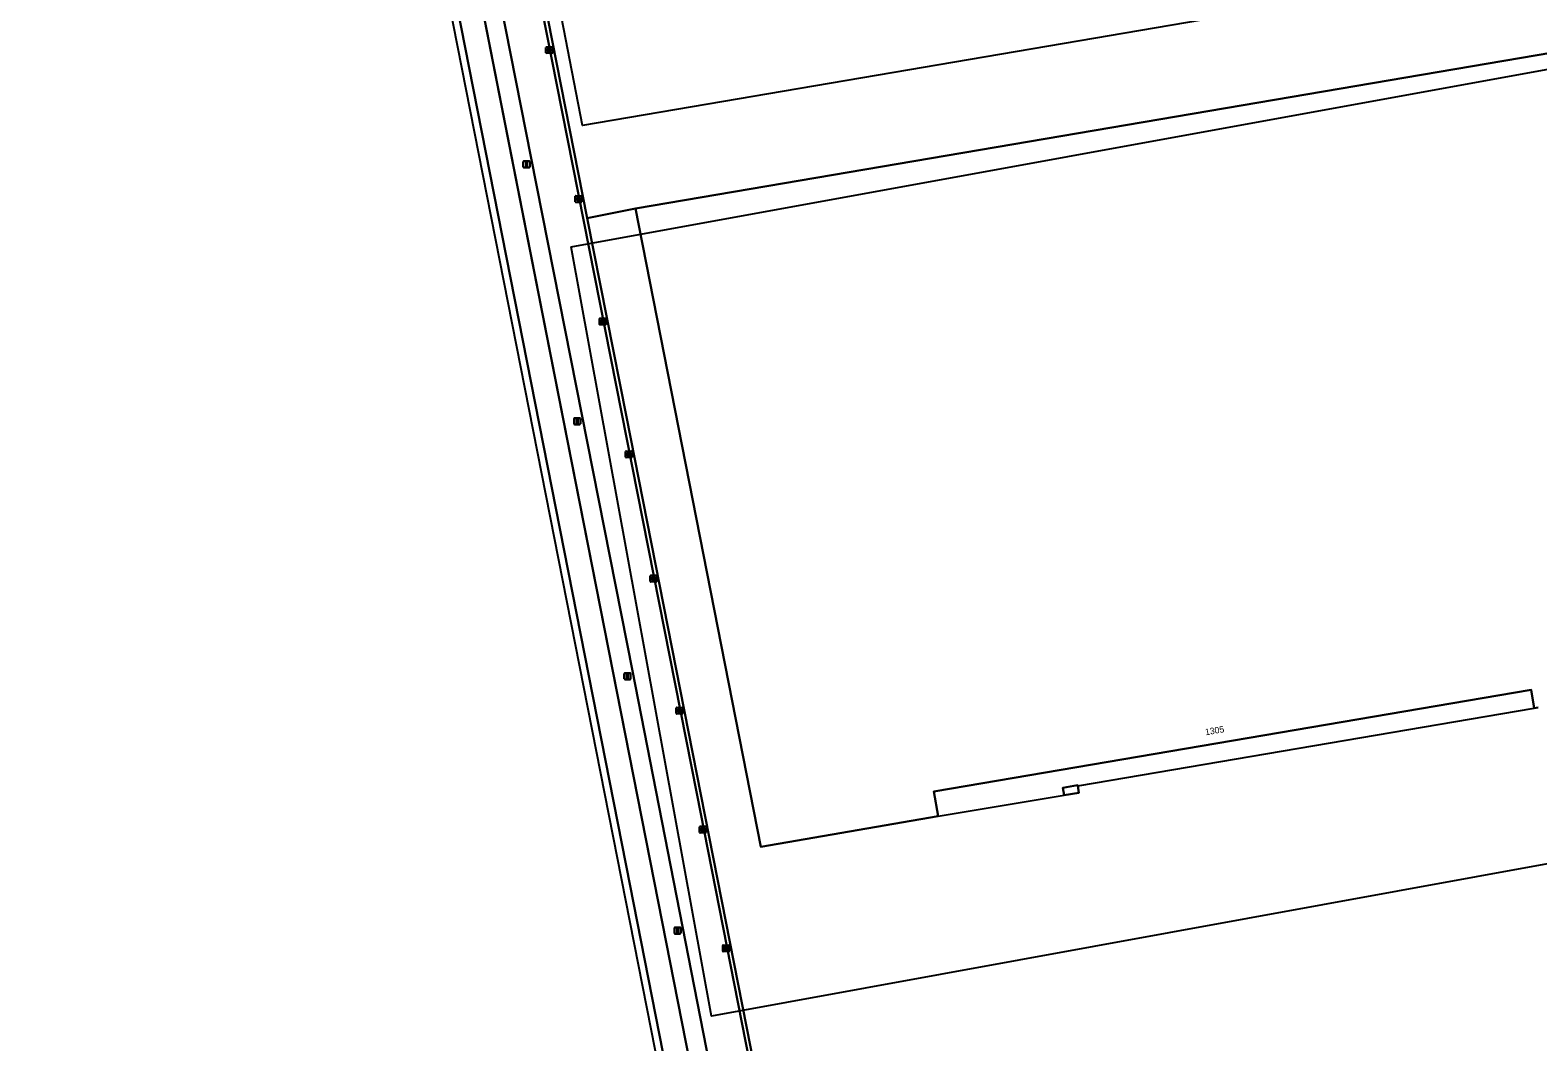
# Model space of a CAD drawing. Extents: x 154324 to 155744, y 382937 to 384188.
# Drawn here: x 154329.4 to 154562, y 383124 to 383280 of the extents above; entities that cross this region are included whole.
import ezdxf

# ---------------------------------------------------------------- set-up
doc = ezdxf.new("R2010")
doc.units = 0
for name, color, linetype in [('IMGEO_Bouwland', 7, 'Continuous'), ('IMGEO_Erf', 7, 'Continuous'), ('IMGEO_Groenvoorziening', 7, 'Continuous'), ('IMGEO_Hek', 7, 'Continuous'), ('IMGEO_Kolk', 7, 'Continuous'), ('IMGEO_Lichtmast', 7, 'Continuous'), ('IMGEO_Loofbos', 7, 'Continuous'), ('IMGEO_Pand', 7, 'Continuous'), ('IMGEO_Pand_nummerreeks', 7, 'Continuous'), ('IMGEO_Pand_overbouw', 7, 'Continuous'), ('IMGEO_Pand_vergunning_verleend', 7, 'Continuous'), ('IMGEO_Rijbaan_lokaal_gesloten', 7, 'Continuous')]:
    doc.layers.add(name, color=color, linetype=linetype)

msp = doc.modelspace()

# ---------------------------------------------------------------- linework, layer by layer
at = {"layer": 'IMGEO_Bouwland'}
for points in [[(154412.15, 383654.94), (154329.44, 383637.33), (154329.96, 383634.71), (154335.86, 383605.18), (154395.89, 383300.08), (154425.66, 383148.76), (154440.92, 383071.1), (154441.6, 383070.12), (154443.07, 383067.76), (154443.58, 383063.68), (154444.38, 383057.2), (154444.57, 383055.85), (154438.63, 383057.42), (154438.84, 383056.38)], [(154461.51, 382981.55), (154450.87, 383035.65), (154439.15, 383095.25), (154422.31, 383181.22), (154406.72, 383260.28), (154396.48, 383312.17), (154394.42, 383322.32), (154392.95, 383329.96)], [(154562.03, 383175.54), (154561.39, 383175.43), (154560.93, 383178.26), (154468.8, 383162.6), (154469.46, 383158.8), (154442.14, 383154.08), (154422.8, 383252.54), (154415.36, 383251.02), (154421.39, 383220.37), (154444.99, 383100.45), (154464.56, 383001.13), (154467.07, 382988.35)]]:
    msp.add_lwpolyline(points, dxfattribs=at)
msp.add_lwpolyline([(154491.18, 383162.38), (154488.9, 383162.01), (154488.72, 383163.17), (154490.98, 383163.56), (154490.99, 383163.49)], close=True, dxfattribs=at)
at = {"layer": 'IMGEO_Erf'}
msp.add_lwpolyline([(154401.25, 383322.6), (154415.36, 383251.02), (154422.8, 383252.54), (154564.29, 383276.58), (154564.29, 383276.6), (154571.56, 383277.87), (154570.67, 383283.11), (154571.25, 383283.17), (154566.84, 383309.22), (154557.23, 383365.65)], dxfattribs=at)
at = {"layer": 'IMGEO_Groenvoorziening'}
msp.add_lwpolyline([(154331.28, 383603.09), (154331.81, 383600.36), (154332.89, 383600.85), (154421.98, 383148.04), (154436.08, 383076.28), (154434.86, 383076.6), (154435.67, 383072.5), (154440.92, 383071.1), (154425.66, 383148.76), (154395.89, 383300.08), (154335.86, 383605.18)], close=True, dxfattribs=at)
at = {"layer": 'IMGEO_Hek'}
msp.add_lwpolyline([(154435.67, 383072.5), (154440.92, 383071.1), (154425.66, 383148.76), (154335.86, 383605.18)], dxfattribs=at)
at = {"layer": 'IMGEO_Kolk'}
for p, q in [((154408.99, 383276.54), (154408.99, 383277.39)), ((154409.07, 383277.47), (154409.92, 383277.47)), ((154409.25, 383276.96), (154409.25, 383276.97)), ((154409.29, 383277.01), (154409.69, 383277.01)), ((154409.69, 383276.92), (154409.29, 383276.92)), ((154409.48, 383277.25), (154409.51, 383277.25)), ((154409.74, 383276.97), (154409.74, 383276.96)), ((154409.99, 383277.39), (154409.99, 383276.54)), ((154409.92, 383276.47), (154409.07, 383276.47)), ((154409.5, 383276.69), (154409.48, 383276.69)), ((154413.51, 383253.56), (154413.51, 383254.41)), ((154413.59, 383254.48), (154414.44, 383254.48)), ((154413.77, 383253.98), (154413.77, 383253.99)), ((154413.81, 383254.03), (154414.21, 383254.03)), ((154414.21, 383253.94), (154413.81, 383253.94)), ((154414, 383254.26), (154414.02, 383254.26)), ((154414.02, 383253.7), (154414, 383253.7)), ((154414.25, 383253.99), (154414.25, 383253.98)), ((154414.51, 383254.41), (154414.51, 383253.56)), ((154414.44, 383253.48), (154413.59, 383253.48)), ((154417.24, 383234.66), (154417.24, 383235.52)), ((154417.31, 383235.59), (154418.16, 383235.59)), ((154417.49, 383235.08), (154417.49, 383235.1)), ((154417.54, 383235.13), (154417.93, 383235.13)), ((154417.72, 383235.37), (154417.75, 383235.37)), ((154417.98, 383235.1), (154417.98, 383235.08)), ((154418.24, 383235.52), (154418.24, 383234.66)), ((154418.16, 383234.59), (154417.31, 383234.59)), ((154417.93, 383235.05), (154417.53, 383235.05)), ((154417.75, 383234.81), (154417.72, 383234.81)), ((154421.26, 383214.18), (154421.26, 383215.03)), ((154421.34, 383215.1), (154422.19, 383215.1)), ((154421.52, 383214.6), (154421.52, 383214.61)), ((154421.56, 383214.65), (154421.96, 383214.65)), ((154421.96, 383214.56), (154421.56, 383214.56)), ((154421.75, 383214.88), (154421.77, 383214.88)), ((154421.77, 383214.32), (154421.75, 383214.32)), ((154422, 383214.61), (154422, 383214.6)), ((154422.26, 383215.03), (154422.26, 383214.18)), ((154422.19, 383214.1), (154421.34, 383214.1)), ((154425.06, 383195.01), (154425.06, 383195.86)), ((154425.13, 383195.94), (154425.99, 383195.94)), ((154425.55, 383195.72), (154425.57, 383195.72)), ((154426.06, 383195.86), (154426.06, 383195.01)), ((154425.99, 383194.94), (154425.13, 383194.94)), ((154425.32, 383195.43), (154425.32, 383195.44)), ((154425.36, 383195.48), (154425.76, 383195.48)), ((154425.76, 383195.39), (154425.36, 383195.39)), ((154425.57, 383195.16), (154425.55, 383195.16)), ((154425.8, 383195.44), (154425.8, 383195.43)), ((154429.09, 383174.64), (154429.09, 383175.5)), ((154429.16, 383175.57), (154430.02, 383175.57)), ((154429.35, 383175.06), (154429.35, 383175.08)), ((154429.39, 383175.11), (154429.79, 383175.11)), ((154429.79, 383175.03), (154429.39, 383175.03)), ((154429.6, 383174.79), (154429.57, 383174.79)), ((154429.58, 383175.35), (154429.6, 383175.35)), ((154429.83, 383175.08), (154429.83, 383175.06)), ((154430.09, 383175.5), (154430.09, 383174.64)), ((154430.02, 383174.57), (154429.16, 383174.57)), ((154432.68, 383156.29), (154432.68, 383157.15)), ((154432.75, 383157.22), (154433.6, 383157.22)), ((154433.6, 383156.22), (154432.75, 383156.22)), ((154432.93, 383156.71), (154432.93, 383156.73)), ((154433.37, 383156.68), (154432.97, 383156.68)), ((154432.98, 383156.76), (154433.38, 383156.76)), ((154433.16, 383157), (154433.19, 383157)), ((154433.19, 383156.44), (154433.16, 383156.44)), ((154433.42, 383156.73), (154433.42, 383156.71)), ((154433.68, 383157.15), (154433.68, 383156.29)), ((154436.26, 383137.98), (154436.26, 383138.83)), ((154436.33, 383138.91), (154437.18, 383138.91)), ((154437.18, 383137.91), (154436.33, 383137.91)), ((154436.51, 383138.4), (154436.51, 383138.41)), ((154436.95, 383138.36), (154436.55, 383138.36)), ((154436.56, 383138.45), (154436.95, 383138.45)), ((154436.74, 383138.69), (154436.77, 383138.69)), ((154436.77, 383138.13), (154436.74, 383138.13)), ((154437, 383138.41), (154437, 383138.4)), ((154437.26, 383138.83), (154437.26, 383137.98))]:
    msp.add_line(p, q, dxfattribs=at)
for points in [[(154408.99, 383276.54), (154408.99, 383277.39)], [(154409.07, 383277.47), (154409.92, 383277.47)], [(154409.99, 383277.39), (154409.99, 383276.54)], [(154409.92, 383276.47), (154409.07, 383276.47)], [(154413.51, 383253.56), (154413.51, 383254.41)], [(154413.59, 383254.48), (154414.44, 383254.48)], [(154414.51, 383254.41), (154414.51, 383253.56)], [(154414.44, 383253.48), (154413.59, 383253.48)], [(154417.24, 383234.66), (154417.24, 383235.52)], [(154417.31, 383235.59), (154418.16, 383235.59)], [(154418.24, 383235.52), (154418.24, 383234.66)], [(154418.16, 383234.59), (154417.31, 383234.59)], [(154421.26, 383214.18), (154421.26, 383215.03)], [(154421.34, 383215.1), (154422.19, 383215.1)], [(154422.26, 383215.03), (154422.26, 383214.18)], [(154422.19, 383214.1), (154421.34, 383214.1)], [(154425.06, 383195.01), (154425.06, 383195.86)], [(154425.13, 383195.94), (154425.99, 383195.94)], [(154426.06, 383195.86), (154426.06, 383195.01)], [(154425.99, 383194.94), (154425.13, 383194.94)], [(154429.09, 383174.64), (154429.09, 383175.5)], [(154429.16, 383175.57), (154430.02, 383175.57)], [(154430.09, 383175.5), (154430.09, 383174.64)], [(154430.02, 383174.57), (154429.16, 383174.57)], [(154432.68, 383156.29), (154432.68, 383157.15)], [(154432.75, 383157.22), (154433.6, 383157.22)], [(154433.6, 383156.22), (154432.75, 383156.22)], [(154433.68, 383157.15), (154433.68, 383156.29)], [(154436.26, 383137.98), (154436.26, 383138.83)], [(154436.33, 383138.91), (154437.18, 383138.91)], [(154437.18, 383137.91), (154436.33, 383137.91)], [(154437.26, 383138.83), (154437.26, 383137.98)]]:
    msp.add_lwpolyline(points, dxfattribs=at)
for centre, radius, start, end in [((154409.07, 383277.39), 0.0765, 91.552, 178.448), ((154409.07, 383277.39), 0.0765, 91.552, 178.448), ((154409.29, 383276.97), 0.0403, 85.8775, 175.7526), ((154409.29, 383276.96), 0.0366, 178.938, 274.7102), ((154409.7, 383276.97), 0.0386, 1.7309, 96.639), ((154409.69, 383276.97), 0.043, 264.8664, 352.4533), ((154409.92, 383277.39), 0.0765, 1.552, 88.448), ((154409.92, 383277.39), 0.0765, 1.552, 88.448), ((154409.07, 383276.54), 0.0765, 181.552, 268.448), ((154409.07, 383276.54), 0.0765, 181.552, 268.448), ((154409.92, 383276.54), 0.0765, 271.552, 358.448), ((154409.92, 383276.54), 0.0765, 271.552, 358.448), ((154413.59, 383254.41), 0.0765, 91.552, 178.448), ((154413.59, 383254.41), 0.0765, 91.552, 178.448), ((154413.81, 383253.99), 0.0403, 85.8775, 175.7526), ((154413.81, 383253.98), 0.0366, 178.938, 274.7102), ((154414.22, 383253.99), 0.0386, 1.7309, 96.639), ((154414.21, 383253.98), 0.043, 264.8664, 352.4533), ((154414.44, 383254.41), 0.0765, 1.552, 88.448), ((154414.44, 383254.41), 0.0765, 1.552, 88.448), ((154413.59, 383253.56), 0.0765, 181.552, 268.448), ((154413.59, 383253.56), 0.0765, 181.552, 268.448), ((154414.44, 383253.56), 0.0765, 271.552, 358.448), ((154414.44, 383253.56), 0.0765, 271.552, 358.448), ((154417.31, 383235.52), 0.0765, 91.552, 178.448), ((154417.31, 383235.52), 0.0765, 91.552, 178.448), ((154417.53, 383235.09), 0.0403, 85.8775, 175.7526), ((154417.53, 383235.08), 0.0366, 178.938, 274.7102), ((154417.94, 383235.1), 0.0386, 1.7309, 96.639), ((154417.94, 383235.09), 0.043, 264.8664, 352.4533), ((154418.16, 383235.52), 0.0765, 1.552, 88.448), ((154418.16, 383235.52), 0.0765, 1.552, 88.448), ((154417.31, 383234.67), 0.0765, 181.552, 268.448), ((154417.31, 383234.67), 0.0765, 181.552, 268.448), ((154418.16, 383234.67), 0.0765, 271.552, 358.448), ((154418.16, 383234.67), 0.0765, 271.552, 358.448), ((154421.34, 383215.03), 0.0765, 91.552, 178.448), ((154421.34, 383215.03), 0.0765, 91.552, 178.448), ((154421.34, 383214.18), 0.0765, 181.552, 268.448), ((154421.34, 383214.18), 0.0765, 181.552, 268.448), ((154421.56, 383214.61), 0.0403, 85.8775, 175.7526), ((154421.56, 383214.6), 0.0366, 178.938, 274.7102), ((154421.97, 383214.61), 0.0386, 1.7309, 96.639), ((154421.96, 383214.6), 0.043, 264.8664, 352.4533), ((154422.19, 383215.03), 0.0765, 1.552, 88.448), ((154422.19, 383215.03), 0.0765, 1.552, 88.448), ((154422.19, 383214.18), 0.0765, 271.552, 358.448), ((154422.19, 383214.18), 0.0765, 271.552, 358.448), ((154425.14, 383195.86), 0.0765, 91.552, 178.448), ((154425.14, 383195.86), 0.0765, 91.552, 178.448), ((154425.98, 383195.86), 0.0765, 1.552, 88.448), ((154425.98, 383195.86), 0.0765, 1.552, 88.448), ((154425.14, 383195.01), 0.0765, 181.552, 268.448), ((154425.14, 383195.01), 0.0765, 181.552, 268.448), ((154425.36, 383195.44), 0.0403, 85.8775, 175.7526), ((154425.36, 383195.43), 0.0366, 178.938, 274.7102), ((154425.76, 383195.44), 0.0386, 1.7309, 96.639), ((154425.76, 383195.44), 0.043, 264.8664, 352.4533), ((154425.98, 383195.01), 0.0765, 271.552, 358.448), ((154425.98, 383195.01), 0.0765, 271.552, 358.448), ((154429.17, 383175.49), 0.0765, 91.552, 178.448), ((154429.17, 383175.49), 0.0765, 91.552, 178.448), ((154429.17, 383174.64), 0.0765, 181.552, 268.448), ((154429.17, 383174.64), 0.0765, 181.552, 268.448), ((154429.39, 383175.07), 0.0403, 85.8775, 175.7526), ((154429.38, 383175.06), 0.0366, 178.938, 274.7102), ((154429.79, 383175.07), 0.0386, 1.7309, 96.639), ((154429.79, 383175.07), 0.043, 264.8664, 352.4533), ((154430.01, 383175.49), 0.0765, 1.552, 88.448), ((154430.01, 383175.49), 0.0765, 1.552, 88.448), ((154430.01, 383174.64), 0.0765, 271.552, 358.448), ((154430.01, 383174.64), 0.0765, 271.552, 358.448), ((154432.75, 383157.14), 0.0765, 91.552, 178.448), ((154432.75, 383157.14), 0.0765, 91.552, 178.448), ((154432.75, 383156.29), 0.0765, 181.552, 268.448), ((154432.75, 383156.29), 0.0765, 181.552, 268.448), ((154432.98, 383156.72), 0.0403, 85.8775, 175.7526), ((154432.97, 383156.71), 0.0366, 178.938, 274.7102), ((154433.38, 383156.72), 0.043, 264.8664, 352.4533), ((154433.38, 383156.72), 0.0386, 1.7309, 96.639), ((154433.6, 383157.14), 0.0765, 1.552, 88.448), ((154433.6, 383157.14), 0.0765, 1.552, 88.448), ((154433.6, 383156.29), 0.0765, 271.552, 358.448), ((154433.6, 383156.29), 0.0765, 271.552, 358.448), ((154436.33, 383138.83), 0.0765, 91.552, 178.448), ((154436.33, 383138.83), 0.0765, 91.552, 178.448), ((154436.33, 383137.98), 0.0765, 181.552, 268.448), ((154436.33, 383137.98), 0.0765, 181.552, 268.448), ((154436.55, 383138.41), 0.0403, 85.8775, 175.7526), ((154436.55, 383138.4), 0.0366, 178.938, 274.7102), ((154436.96, 383138.41), 0.0386, 1.7309, 96.639), ((154436.96, 383138.41), 0.043, 264.8664, 352.4533), ((154437.18, 383138.83), 0.0765, 1.552, 88.448), ((154437.18, 383138.83), 0.0765, 1.552, 88.448), ((154437.18, 383137.98), 0.0765, 271.552, 358.448), ((154437.18, 383137.98), 0.0765, 271.552, 358.448)]:
    msp.add_arc(centre, radius, start, end, dxfattribs=at)
for centre, major_axis, ratio, start_param, end_param in [((154409.48, 383276.97), (-0.387, 0.002), 0.722429, 4.712389, 7.853982), ((154409.5, 383276.97), (-0.39, 0.002), 0.717154, 1.570796, 4.712389), ((154414, 383253.98), (-0.387, 0.002), 0.722429, 4.712389, 7.853982), ((154414.02, 383253.98), (-0.39, 0.002), 0.717154, 1.570796, 4.712389), ((154417.72, 383235.09), (-0.387, 0.002), 0.722429, 4.712389, 7.853982), ((154417.75, 383235.09), (-0.39, 0.002), 0.717154, 1.570796, 4.712389), ((154421.75, 383214.6), (-0.387, 0.002), 0.722429, 4.712389, 7.853982), ((154421.77, 383214.6), (-0.39, 0.002), 0.717154, 1.570796, 4.712389), ((154425.55, 383195.44), (-0.387, 0.002), 0.722429, 4.712389, 7.853982), ((154425.57, 383195.44), (-0.39, 0.002), 0.717154, 1.570796, 4.712389), ((154429.58, 383175.07), (-0.387, 0.002), 0.722429, 4.712389, 7.853982), ((154429.6, 383175.07), (-0.39, 0.002), 0.717154, 1.570796, 4.712389), ((154433.16, 383156.72), (-0.387, 0.002), 0.722429, 4.712389, 7.853982), ((154433.19, 383156.72), (-0.39, 0.002), 0.717154, 1.570796, 4.712389), ((154436.74, 383138.41), (-0.387, 0.002), 0.722429, 4.712389, 7.853982), ((154436.77, 383138.41), (-0.39, 0.002), 0.717154, 1.570796, 4.712389)]:
    msp.add_ellipse(centre, major_axis=major_axis, ratio=ratio, start_param=start_param, end_param=end_param, dxfattribs=at)
at = {"layer": 'IMGEO_Lichtmast'}
for p, q in [((154405.49, 383258.94), (154405.49, 383259.74)), ((154405.49, 383259.74), (154405.49, 383258.94)), ((154405.59, 383259.84), (154406.38, 383259.84)), ((154406.38, 383259.84), (154405.59, 383259.84)), ((154406.38, 383258.84), (154405.59, 383258.84)), ((154405.59, 383258.84), (154406.38, 383258.84)), ((154406.48, 383259.74), (154406.48, 383258.94)), ((154406.48, 383258.94), (154406.48, 383259.74)), ((154413.32, 383219.31), (154413.32, 383220.11)), ((154413.32, 383220.11), (154413.32, 383219.31)), ((154413.42, 383220.21), (154414.21, 383220.21)), ((154414.21, 383220.21), (154413.42, 383220.21)), ((154414.21, 383219.21), (154413.42, 383219.21)), ((154413.42, 383219.21), (154414.21, 383219.21)), ((154414.31, 383220.11), (154414.31, 383219.31)), ((154414.31, 383219.31), (154414.31, 383220.11)), ((154421.05, 383179.97), (154421.05, 383180.77)), ((154421.05, 383180.77), (154421.05, 383179.97)), ((154421.15, 383180.87), (154421.94, 383180.87)), ((154421.94, 383180.87), (154421.15, 383180.87)), ((154421.94, 383179.87), (154421.15, 383179.87)), ((154421.15, 383179.87), (154421.94, 383179.87)), ((154422.04, 383180.77), (154422.04, 383179.97)), ((154422.04, 383179.97), (154422.04, 383180.77)), ((154428.79, 383140.73), (154428.79, 383141.52)), ((154428.79, 383141.52), (154428.79, 383140.73)), ((154428.89, 383141.62), (154429.68, 383141.62)), ((154429.68, 383141.62), (154428.89, 383141.62)), ((154429.68, 383140.63), (154428.89, 383140.63)), ((154428.89, 383140.63), (154429.68, 383140.63)), ((154429.78, 383141.52), (154429.78, 383140.73)), ((154429.78, 383140.73), (154429.78, 383141.52))]:
    msp.add_line(p, q, dxfattribs=at)
for points in [[(154405.91, 383259.71), (154406.06, 383259.71), (154406.06, 383258.96), (154405.91, 383258.96), (154405.91, 383259.71)], [(154413.74, 383220.09), (154413.89, 383220.09), (154413.89, 383219.34), (154413.74, 383219.34), (154413.74, 383220.09)], [(154421.47, 383180.74), (154421.62, 383180.74), (154421.62, 383179.99), (154421.47, 383179.99), (154421.47, 383180.74)], [(154429.21, 383141.5), (154429.36, 383141.5), (154429.36, 383140.75), (154429.21, 383140.75), (154429.21, 383141.5)]]:
    msp.add_lwpolyline(points, dxfattribs=at)
for centre, start, end in [((154405.59, 383259.74), 90, 180), ((154405.59, 383259.74), 90, 180), ((154405.59, 383258.94), 180, 270), ((154405.59, 383258.94), 180, 270), ((154406.38, 383259.74), 0, 90), ((154406.38, 383259.74), 360, 90), ((154406.38, 383258.94), 270, 0), ((154406.38, 383258.94), 270, 0), ((154413.42, 383220.11), 90, 180), ((154413.42, 383220.11), 90, 180), ((154413.42, 383219.31), 180, 270), ((154413.42, 383219.31), 180, 270), ((154414.21, 383220.11), 0, 90), ((154414.21, 383220.11), 360, 90), ((154414.21, 383219.31), 270, 0), ((154414.21, 383219.31), 270, 0), ((154421.15, 383180.77), 90, 180), ((154421.15, 383180.77), 90, 180), ((154421.15, 383179.97), 180, 270), ((154421.15, 383179.97), 180, 270), ((154421.94, 383180.77), 0, 90), ((154421.94, 383180.77), 360, 90), ((154421.94, 383179.97), 270, 0), ((154421.94, 383179.97), 270, 0), ((154428.89, 383141.52), 90, 180), ((154428.89, 383141.52), 90, 180), ((154428.89, 383140.73), 180, 270), ((154428.89, 383140.73), 180, 270), ((154429.68, 383141.52), 0, 90), ((154429.68, 383141.52), 360, 90), ((154429.68, 383140.73), 270, 0), ((154429.68, 383140.73), 270, 0)]:
    msp.add_arc(centre, 0.1, start, end, dxfattribs=at)
at = {"layer": 'IMGEO_Loofbos'}
msp.add_lwpolyline([(154434.86, 383076.6), (154436.08, 383076.28), (154421.98, 383148.04), (154332.89, 383600.85), (154331.81, 383600.36)], close=True, dxfattribs=at)
at = {"layer": 'IMGEO_Pand'}
msp.add_lwpolyline([(154564.29, 383276.58), (154422.8, 383252.54), (154442.14, 383154.08), (154469.46, 383158.8), (154468.8, 383162.6), (154560.93, 383178.26), (154561.39, 383175.43), (154562.03, 383175.54)], dxfattribs=at)
msp.add_lwpolyline([(154490.98, 383163.56), (154488.72, 383163.17), (154488.9, 383162.01), (154491.18, 383162.38), (154490.99, 383163.49)], close=True, dxfattribs=at)
at = {"layer": 'IMGEO_Pand_overbouw'}
msp.add_lwpolyline([(154469.46, 383158.8), (154488.9, 383162.01), (154491.18, 383162.38), (154490.99, 383163.49), (154561.39, 383175.43), (154560.93, 383178.26), (154468.8, 383162.6)], close=True, dxfattribs=at)
at = {"layer": 'IMGEO_Pand_vergunning_verleend'}
msp.add_lwpolyline([(154548.37, 383288.17), (154414.6, 383265.31), (154403.03, 383325.33)], dxfattribs=at)
msp.add_lwpolyline([(154412.9, 383246.6), (154566.07, 383274.51), (154587.69, 383155.85), (154434.52, 383127.94)], close=True, dxfattribs=at)
at = {"layer": 'IMGEO_Rijbaan_lokaal_gesloten'}
for points in [[(154392.95, 383329.96), (154394.42, 383322.32), (154396.48, 383312.17), (154406.72, 383260.28), (154422.31, 383181.22), (154439.15, 383095.25), (154450.87, 383035.65), (154461.51, 382981.55)], [(154400.66, 383322.48), (154411.51, 383267.43), (154432.24, 383162.26), (154453.69, 383053.15), (154463.94, 383001.02), (154466.46, 382988.22)], [(154466.46, 382988.22), (154463.94, 383001.02), (154453.69, 383053.15), (154432.24, 383162.26), (154411.51, 383267.43), (154400.66, 383322.48)], [(154467.07, 382988.35), (154464.56, 383001.13), (154444.99, 383100.45), (154421.39, 383220.37), (154415.36, 383251.02), (154401.25, 383322.6)]]:
    msp.add_lwpolyline(points, dxfattribs=at)

# ---------------------------------------------------------------- texts
at = {"layer": 'IMGEO_Pand_nummerreeks'}
msp.add_text('1305', height=1, rotation=9.6429, dxfattribs=at).set_placement((154510.72, 383171.25))

doc.saveas('drawing.dxf')
